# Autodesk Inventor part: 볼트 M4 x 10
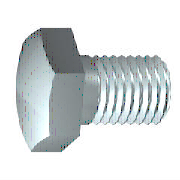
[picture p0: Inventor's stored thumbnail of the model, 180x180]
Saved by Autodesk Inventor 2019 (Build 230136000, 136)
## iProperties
Created: 2012-02
Part Number: 볼트 M4 x 10
Material: 스테인리스강
Description: 6각 머리 나사
Document SubType Name: Modeling
Standard: ISO 4017
Designer: mduedu
Standard Revision: Third edition 1999-08-15
Standards Organization: ISO
Language: ko-KR
Size Designation: M4 x 10
Categories: <MemberInstance><Categories><Category DisplayName="조임쇠" InternalName="e4da775c-781d-43d5-af7c-5136215cf5a6" Mnemonic="FSTN"><Category DisplayName="볼트" InternalN
Density: 8.08 g/cm^3
Appearance: 기본값
IsCustomPart: 0
Author: mduedu
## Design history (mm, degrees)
sketch "스케치1"
  geometry: L1 (0, 3.015)-(0, 2); L2 (2.1, 2)-(10, 2); L3 (10, 2)-(10, 0); L4 (10, 0)-(-0.4, 0); L5 (-2.48, 0)-(12.08, 0) reference; L6 (-0.4, 0)-(-0.4, 3.015); L7 (-0.4, 3.015)-(0, 3.015); L8 (2.1, 2)-(1.67, 2); L9 (1.67, 2)-(0, 2); L10 (0, -0.603)-(0, 3.618) reference
  constraints: 16 end point, 2 collinear, 2 perpendicular, 1 parallel
  dimensions: "d0" = 10 distance between parallel lines of L3 L1 (= NLG); "d1" = 7.9 distance from line of L2.start L3 (= GEL); "d2" = 4 diameter of L2 L4 (= GD); "d9" = 0.4001 distance between parallel lines of L6 L1 (computed from SD); "d10" = 6.03 diameter of L7 L4 (= SD2); "d13" = 0.42952 distance of L2.start L8.end (computed from GAL); "d14" = 4 diameter of L9 L4 (= BDM)
revolve "본체" sketch "스케치1" stored, may be unused: angle "d12" = 90 deg
sketch "스케치2"
  geometry: L1 (0, 4.041)-(3.5, 2.021); L2 (3.5, 2.021)-(3.5, -2.021); L3 (3.5, -2.021)-(0, -4.041); L4 (0, -4.041)-(-3.5, -2.021); L5 (-3.5, -2.021)-(-3.5, 2.021); L6 (-3.5, 2.021)-(0, 4.041); 2 further points
  constraints: 12 end point, 1 coincident, 1 vertical, 11 other
  dimensions: "d11" = 7 distance between parallel lines of L5 L2 (= SW)
extrude "머리" join sketch "스케치2" distance "d3" = 2.4 (= KOH - SD); taper "d4" = 0 deg
sketch "스케치4"
  geometry: L1 (-2.8, 3.5)-(-2.8, 4.041); L2 (-2.8, 4.041)-(-2.487, 4.041); L3 (-2.487, 4.041)-(-2.8, 3.5); L4 (-3.28, 0)-(0.08, 0) reference; L5 (-0.4, 4.041)-(-2.8, 4.041) reference; L6 (-2.8, 2.021)-(-2.8, 4.041) reference
  constraints: 6 end point, 2 collinear, 1 perpendicular, 1 vertical
  dimensions: "d5" = 30 deg angle of L3 L1 (= ANG1); "d19" = 7 diameter of L1.start L4 (= SW0)
revolve "모따기1" sketch "스케치4" stored, may be unused: angle "d21" = 90 deg
workplane "Work Plane1"
body "Solid1"
feature "스레드" dims "d15" = 7.9 (= GEL), "d16" = 0
chamfer "모따기2" distance "d6" = 0.42941 (= -0.5 x SPD + 0.5 x GD); stored, may be unused: second distance "d7" = 0.42952 (computed from GUL), angle "d55" = 45 deg
other parameters: "NLG" = 10 [user parameter; used in 1 equation term], "GD" = 4 (= NND) [user parameter; used in 2 equation terms], "BDM" = 4 (= NND) [user parameter; used in 1 equation term], "KOH" = 2.8 [user parameter; used in 1 equation term], "GEL" = 7.9 [user parameter; used in 2 equation terms], "SW" = 7 [user parameter; used in 2 equation terms], "SW0" = 7 (= SW) [user parameter; used in 1 equation term], "SPD" = 3.14117 (= NND - 1.2269 x PTC) [user parameter; used in 1 equation term], "SD2" = 6.03 [user parameter; used in 2 equation terms], "SD" = 0.4 [user parameter; used in 2 equation terms], "ANG1" = 30 deg [user parameter; used in 1 equation term], "GAL" = 0.42941 (= 0.61345 x PTC) [user parameter; used in 1 equation term], "GUL" = 0.42941 (= 0.61345 x PTC) [user parameter; used in 1 equation term], "d8" = 0, "RR" = 0.2 [user parameter], "d57" = 0, "d58" = 0, "TPU" = 14.28571 (computed from PTC) [user parameter], "GD1" = 3.14117 (= THREADDIA - 1.2269 x PTC) [user parameter], "THREADDIA" = 4 [user parameter; used in 1 equation term], "SDH" = 6.03 (= SD2) [user parameter], "SDHG" = 2.1 [user parameter], "TOA" = 30 deg [user parameter], "PTC" = 0.7 [user parameter; used in 5 equation terms], "NND" = 4 [user parameter; used in 3 equation terms], "E0" = 8.085 [user parameter]
